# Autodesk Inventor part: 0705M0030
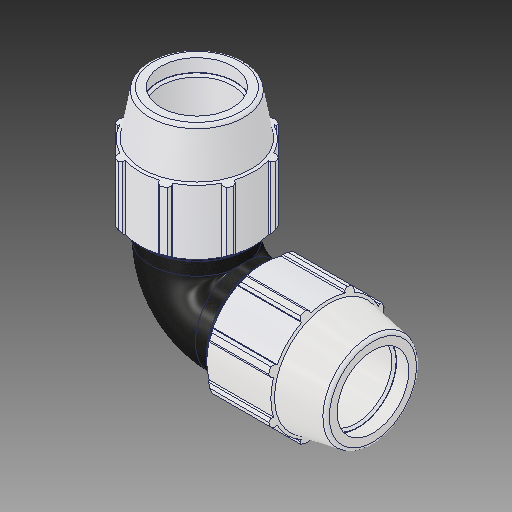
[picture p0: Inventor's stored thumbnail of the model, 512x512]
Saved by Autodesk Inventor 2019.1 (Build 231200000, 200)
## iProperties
Created: 2017-02
Part Number: 0705M0030
Material: PVC-Piping
Description: PLASSON 90° ELBOW 3'' - 3''
Document SubType Name: Modeling
Designer: KIM
Mass: 92.6774 g
Surface Area: 199.44 cm^2
Volume: 66.1981 cm^3
Density: 1.4 g/cm^3
Appearance: PTFE
Author: KIM
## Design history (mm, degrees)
derived "0705M0.ipt"
feature "Solid1::0705M0.ipt"
tag "TaggingFeature1"
body "Solid1"
other parameters: "d2" = 88.7, "d4" = 18.161, "d5" = 54.483, "d7" = 151.892, "d9" = 31.13314, "d11" = 5.4483, "d13" = 120 deg, "d14" = 115.31, "d15" = 10 deg, "d16" = 132.14604, "d18" = 4.435, "d19" = 35 deg, "d20" = 17.5 deg, "d21" = 141.25956, "d23" = 0, "d25" = 360 deg, "d27" = 3.03784, "d33" = 1.774, "d42" = 80.63484, "d43" = 4.55676, "d46" = 2.661, "d51" = 217.932, "d59" = 90 deg, "d63" = 162.814, "d64" = 79.83, "d67" = 113.919, "d68" = 1.36207, "d70" = 90 deg, "d_" = 88.7, "E_" = 151.892, "A_" = 217.932, "l_" = 162.814
